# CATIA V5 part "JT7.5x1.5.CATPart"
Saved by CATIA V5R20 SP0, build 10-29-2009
Part number: JT7.5x1.5
Revision: ANY
Definition: UNKNOWN
Nomenclature: JT7.5x1.5
Source: Unknown
Bounding box of the stored display mesh (mm): x -5.25 to 5.25, y -0.75 to 0.75, z -5.25 to 5.25
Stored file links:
  C:\Users\Utente\Desktop\IO LAVORO\3D X SITO CF\CUMSA\3D files SA\SA 120014\JT7.5x1.5.CATPart
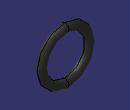
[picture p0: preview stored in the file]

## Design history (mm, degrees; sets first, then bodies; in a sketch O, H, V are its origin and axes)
Body1 "Revolución1" (main body)
  Solid1: solid without history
